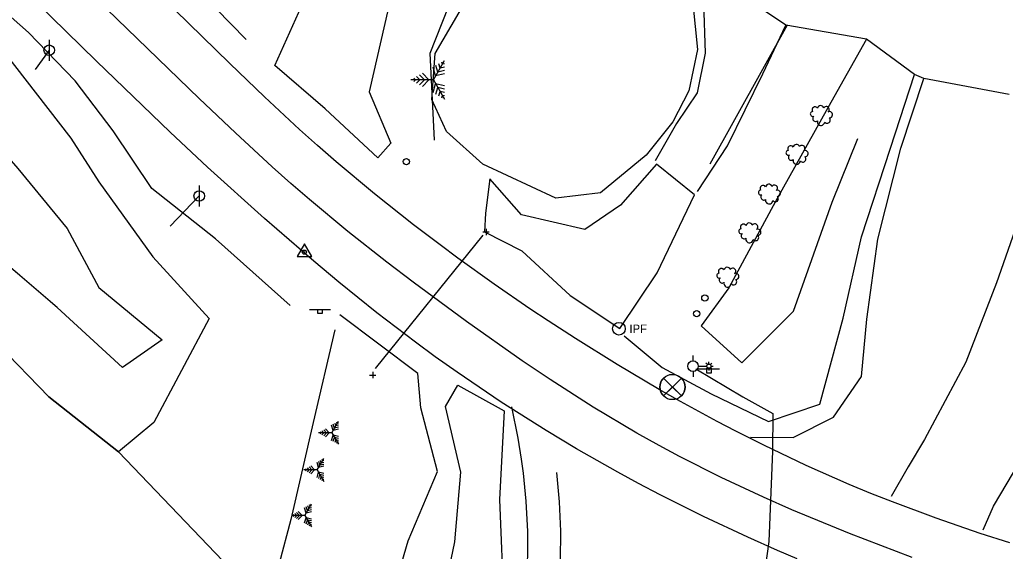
# Model space of a CAD drawing. Extents: x 1158469 to 1165378, y 609843 to 611748.
# Drawn here: x 1158676 to 1158909.5, y 611390 to 611516 of the extents above; entities that cross this region are included whole.
import ezdxf

# ---------------------------------------------------------------- set-up
doc = ezdxf.new("R2010")
doc.units = 0
for name, color, linetype in [('Exterior Boundary', 7, 'Continuous'), ('S_Control_Temp_Traverse', 7, 'Continuous'), ('S_Drainage_Culvert_Top', 7, 'Continuous'), ('S_Drainage_Invert', 7, 'Continuous'), ('S_Drainage_Waterway', 7, 'Continuous'), ('S_Fencing_Page', 7, 'Continuous'), ('S_Ground_Elevation', 7, 'Continuous'), ('S_Property_IronPipeFound', 7, 'Continuous'), ('S_Roadway_Centerline', 7, 'Continuous'), ('S_Roadway_Drive_Gravel', 7, 'Continuous'), ('S_Roadway_Edge_Pavement', 7, 'Continuous'), ('S_Roadway_Edge_TW', 7, 'Continuous'), ('S_Traffic_Post_Conc', 7, 'Continuous'), ('S_Traffic_Sign_SinglePost', 7, 'Continuous'), ('S_Trees_Bush', 7, 'Continuous'), ('S_Trees_Conifer_NonPay', 7, 'Continuous'), ('S_Trees_Conifer_Pay', 7, 'Continuous'), ('S_Trees_HedgeLine', 7, 'Continuous'), ('S_Utilities_GuyWire3', 7, 'Continuous'), ('S_Utilities_Pole_Power', 7, 'Continuous'), ('S_Utilities_Pole_StreetLight', 7, 'Continuous'), ('S_Utilities_UG_BoringLocation', 7, 'Continuous'), ('S_Utilities_UG_Electrical_Line', 7, 'Continuous')]:
    doc.layers.add(name, color=color, linetype=linetype)

msp = doc.modelspace()

# ---------------------------------------------------------------- linework, layer by layer
at = {"layer": 'Exterior Boundary'}
for points in [[(1158910.45, 611498.3), (1158890.25, 611502.09), (1158888.06, 611503.01), (1158876.65, 611511.4), (1158857.5, 611514.75), (1158825.21, 611536.33)], [(1158670.67, 611439.15), (1158682.9, 611426.67), (1158699.39, 611413.61), (1158734.7, 611376.73), (1158730.76, 611361.06), (1158748.32, 611349.64), (1158760.71, 611343.05), (1158765.36, 611317.58), (1158768.71, 611314.29), (1158775.07, 611309.36), (1158788.22, 611303.65), (1158800.68, 611297.03), (1158808.24, 611293.89), (1158811.71, 611292.65), (1158828.39, 611280.44), (1158844.21, 611270.14), (1158861.97, 611263.38), (1158876.73, 611255.65), (1158889.33, 611276.16), (1158914.58, 611278.16)]]:
    msp.add_lwpolyline(points, dxfattribs=at)
at = {"layer": 'S_Control_Temp_Traverse'}
for p, q in [((1158743.3, 611460.92), (1158743.55, 611460.92)), ((1158743.42, 611461.05), (1158743.42, 611460.8))]:
    msp.add_line(p, q, dxfattribs=at)
msp.add_lwpolyline([(1158741.69, 611459.92), (1158745.16, 611459.92), (1158743.42, 611462.92)], close=True, dxfattribs=at)
msp.add_circle((1158743.42, 611460.92), 0.5, dxfattribs=at)
at = {"layer": 'S_Drainage_Culvert_Top'}
msp.add_lwpolyline([(1158785.74, 611464.98), (1158760.24, 611433.33)], dxfattribs=at)
at = {"layer": 'S_Drainage_Invert'}
for p, q in [((1158785.73, 611465.71), (1158787.23, 611465.71)), ((1158786.48, 611466.46), (1158786.48, 611464.96)), ((1158758.88, 611431.79), (1158760.38, 611431.79)), ((1158759.63, 611432.54), (1158759.63, 611431.04))]:
    msp.add_line(p, q, dxfattribs=at)
at = {"layer": 'S_Drainage_Waterway'}
msp.add_lwpolyline([(1158785.74, 611481.8), (1158777.15, 611489.55), (1158773.6, 611497.1), (1158774.43, 611508), (1158780.14, 611517.71), (1158786.58, 611529.17), (1158799.68, 611540.94), (1158809.55, 611542.02), (1158823.95, 611534.62), (1158835.49, 611519.84), (1158836.62, 611508.98), (1158834.58, 611499.17), (1158830.73, 611491.78), (1158824.45, 611483.92), (1158813.6, 611474.99), (1158803.06, 611473.68)], close=True, dxfattribs=at)
at = {"layer": 'S_Fencing_Page'}
msp.add_lwpolyline([(1158750.67, 611442.48), (1158745.54, 611420.52), (1158740.24, 611397.56), (1158734.7, 611376.73), (1158730.76, 611361.06)], dxfattribs=at)
at = {"layer": 'S_Ground_Elevation'}
for points in [[(1158740.09, 611448.28), (1158722.35, 611464.08), (1158707.31, 611475.97), (1158698.09, 611489.64), (1158689.14, 611501.5), (1158678.07, 611512.98), (1158662.14, 611527.03), (1158643.93, 611543.97), (1158624.15, 611563.13), (1158596.77, 611589.62)], [(1158808.66, 611546.24), (1158790.91, 611556.33), (1158774.35, 611541), (1158763.38, 611518.91), (1158758.8, 611498.89), (1158763.92, 611486.74), (1158760.8, 611483.29), (1158748.32, 611494.91), (1158736.46, 611505.19), (1158743.56, 611521.02), (1158754.04, 611539.22), (1158761.64, 611558.27), (1158767.55, 611571.39), (1158747.46, 611585.83), (1158737.58, 611570.89), (1158726.51, 611554.87), (1158719.26, 611542.74), (1158716.56, 611529.56), (1158722.45, 611518.66), (1158729.61, 611511.28)], [(1158590.85, 611583.59), (1158615.18, 611558.04), (1158629.09, 611543.1), (1158650.93, 611520), (1158669.17, 611512.21), (1158688.09, 611487.97), (1158694.7, 611477.56), (1158707.55, 611459.8), (1158720.85, 611445.22), (1158707.76, 611420.56), (1158699.39, 611413.61), (1158682.9, 611426.67), (1158670.67, 611439.15), (1158654.72, 611451.38), (1158635.01, 611471.5), (1158613.25, 611484.43), (1158585.12, 611500.58), (1158568.33, 611515.58)], [(1158580.71, 611570.3), (1158596.17, 611552.09), (1158620.52, 611526.83), (1158638.48, 611508.6), (1158660.2, 611498.31), (1158675.5, 611480.75), (1158687.22, 611466.53), (1158694.73, 611452.55), (1158709.71, 611440.16), (1158700.35, 611433.55), (1158684.85, 611447.82), (1158665.43, 611464.41), (1158653.02, 611480.25), (1158622.81, 611498.8), (1158603.19, 611517), (1158575.66, 611532.02), (1158562.58, 611545.77)], [(1158774.24, 611487.44), (1158773.21, 611508.05), (1158777.62, 611519.03), (1158785.53, 611530.88), (1158792.69, 611538.6), (1158803.21, 611544.63), (1158811.27, 611543.77), (1158825.21, 611536.33), (1158838.01, 611520.07), (1158838.43, 611508.04), (1158836.52, 611498.69), (1158831.59, 611491.44), (1158826.6, 611482.59)], [(1158836.58, 611475.29), (1158843.71, 611486.11), (1158852.11, 611503.19), (1158857.5, 611514.75)], [(1158819.2, 611441.05), (1158828.22, 611433.55), (1158839.8, 611427.34), (1158853.43, 611420.78), (1158865.56, 611424.89), (1158871.1, 611445.26), (1158875.5, 611464.56), (1158882.32, 611485.55), (1158888.06, 611503.01), (1158876.65, 611511.4), (1158867.51, 611495.16), (1158855.12, 611472.93), (1158844, 611452.47), (1158837.45, 611443.47), (1158847.09, 611434.67), (1158859.35, 611446.93), (1158868.53, 611472.76), (1158874.57, 611487.84)], [(1158904.32, 611395.15), (1158906.79, 611400.72), (1158916.02, 611416.31), (1158924.09, 611434.05), (1158932.36, 611453.59), (1158941.22, 611470.3), (1158947.06, 611480.27), (1158932.94, 611486.27), (1158930.52, 611481.92), (1158922.93, 611484.99), (1158913.99, 611472.35), (1158907.43, 611453.65), (1158900.18, 611434.86), (1158890.38, 611416.5), (1158886.53, 611410.08), (1158882.51, 611403.01)], [(1158748.32, 611349.64), (1158761.67, 611370.85), (1158768.02, 611392.49), (1158774.99, 611408.97), (1158771.02, 611424.01), (1158770.29, 611432.13), (1158751.86, 611446.05)], [(1158750.67, 611442.48), (1158745.54, 611420.52), (1158740.24, 611397.56), (1158734.7, 611376.73), (1158730.76, 611361.06)], [(1158760.71, 611343.05), (1158773.56, 611365.65), (1158779.05, 611392.3), (1158780.47, 611408.74), (1158776.85, 611424.34), (1158779.76, 611429.39), (1158790.77, 611423.33), (1158789.65, 611402.27), (1158790.72, 611377.04), (1158784.12, 611354), (1158765.36, 611317.58)]]:
    msp.add_lwpolyline(points, dxfattribs=at)
msp.add_lwpolyline([(1158787.4, 611478.32), (1158786.33, 611470.19), (1158786.11, 611465.72), (1158794.97, 611461.22), (1158806.44, 611450.67), (1158818.21, 611442.8), (1158827.03, 611456.05), (1158835.92, 611474.48), (1158826.85, 611481.78), (1158818.38, 611472.07), (1158809.87, 611466.29), (1158794.88, 611469.73)], close=True, dxfattribs=at)
at = {"layer": 'S_Property_IronPipeFound'}
msp.add_circle((1158817.97, 611442.76), 1.5, dxfattribs=at)
at = {"layer": 'S_Roadway_Centerline'}
msp.add_lwpolyline([(1158887.44, 611388.58), (1158872.59, 611394.24), (1158858.97, 611399.85), (1158852.23, 611402.82), (1158842.21, 611407.49), (1158832.35, 611412.46), (1158827.48, 611415.07), (1158822.23, 611418.02), (1158811.88, 611424.2), (1158801.72, 611430.71), (1158795.04, 611435.2), (1158781.87, 611444.46), (1158769.21, 611453.77), (1158762.97, 611458.54), (1158753.73, 611465.84), (1158744.68, 611473.36), (1158740.23, 611477.2), (1158735.8, 611481.14), (1158727.08, 611489.17), (1158718.49, 611497.35), (1158701.46, 611513.88), (1158679.55, 611535.06)], dxfattribs=at)
at = {"layer": 'S_Roadway_Drive_Gravel'}
msp.add_lwpolyline([(1158849.13, 611417.04), (1158859.3, 611417), (1158868.8, 611421.81), (1158875.5, 611431.43), (1158876.76, 611445.05), (1158879.32, 611463.97), (1158884.77, 611485.57), (1158890.25, 611502.09)], dxfattribs=at)
at = {"layer": 'S_Roadway_Edge_Pavement'}
for points in [[(1158910.66, 611392.01), (1158903.63, 611394.28), (1158893.17, 611397.88), (1158882.8, 611401.72), (1158877.66, 611403.76), (1158872.53, 611405.88), (1158862.36, 611410.37), (1158852.3, 611415.16), (1158845.67, 611418.51), (1158841.28, 611420.81), (1158832.59, 611425.54), (1158827.53, 611428.4), (1158817.53, 611434.31), (1158807.67, 611440.44), (1158801.17, 611444.65), (1158796.88, 611447.52), (1158788.37, 611453.36), (1158779.82, 611459.49), (1158775.6, 611462.62), (1158769.32, 611467.39), (1158760.05, 611474.74), (1158750.98, 611482.33), (1158746.53, 611486.22), (1158742.29, 611490.01), (1158733.95, 611497.75), (1158725.73, 611505.63), (1158709.47, 611521.56)], [(1158860.25, 611388.2), (1158855.54, 611390.23), (1158848.51, 611393.36), (1158838.06, 611398.26), (1158827.73, 611403.43), (1158822.62, 611406.11), (1158817.69, 611408.78), (1158807.93, 611414.32), (1158800.71, 611418.64), (1158790.05, 611425.4), (1158779.6, 611432.47), (1158774.46, 611436.12), (1158769.8, 611439.55), (1158760.6, 611446.57), (1158751.58, 611453.82), (1158745.66, 611458.76), (1158733.99, 611468.86), (1158720.5, 611481.08), (1158711.64, 611489.37), (1158694.13, 611506.17), (1158679.83, 611520.15)], [(1158792.52, 611424.23), (1158794.05, 611416.81), (1158794.84, 611411.85), (1158795.28, 611408.54), (1158795.92, 611401.88), (1158796.28, 611394.7), (1158796.32, 611391.1), (1158796.21, 611385.69), (1158795.87, 611380.29), (1158795.62, 611377.6), (1158794.95, 611372.37), (1158794.51, 611369.78), (1158793.7, 611365.91), (1158792.67, 611362.1), (1158792.08, 611360.21), (1158790.69, 611356.49), (1158789.9, 611354.66), (1158788.57, 611351.95), (1158768.71, 611314.29)]]:
    msp.add_lwpolyline(points, dxfattribs=at)
at = {"layer": 'S_Roadway_Edge_TW'}
msp.add_lwpolyline([(1158803.15, 611408.66), (1158803.84, 611401.73), (1158804.14, 611394.77), (1158804.03, 611387.81), (1158803.52, 611380.86), (1158802.62, 611373.95), (1158801.32, 611367.11), (1158799.63, 611360.35), (1158797.56, 611353.7), (1158795.53, 611348.23), (1158775.07, 611309.36)], dxfattribs=at)
at = {"layer": 'S_Traffic_Post_Conc'}
for centre in [(1158767.61, 611482.38), (1158838.34, 611450.05), (1158836.42, 611446.34)]:
    msp.add_circle(centre, 0.75, dxfattribs=at)
at = {"layer": 'S_Traffic_Sign_SinglePost'}
for p, q in [((1158744.65, 611447.36), (1158749.65, 611447.36)), ((1158836.83, 611433.27), (1158841.83, 611433.27))]:
    msp.add_line(p, q, dxfattribs=at)
for points in [[(1158746.65, 611447.36), (1158747.65, 611447.36), (1158747.65, 611446.36), (1158746.65, 611446.36)], [(1158838.83, 611433.27), (1158839.83, 611433.27), (1158839.83, 611432.27), (1158838.83, 611432.27)]]:
    msp.add_lwpolyline(points, close=True, dxfattribs=at)
at = {"layer": 'S_Trees_Bush'}
for centre, radius, start, end in [((1158864.45, 611494.64), 0.717, 33.6405, 213.5909), ((1158865.81, 611494.88), 0.776, 19.7277, 168.0032), ((1158867.13, 611494.73), 0.715, 304.7168, 145.2832), ((1158863.91, 611493.67), 0.576, 95.1875, 295.4615), ((1158864.6, 611492.6), 0.706, 129.1555, 309.4105), ((1158867.33, 611492.21), 0.742, 216.9809, 47.4965), ((1158867.85, 611493.49), 0.733, 268.122, 116.0172), ((1158865.88, 611491.82), 0.862, 163.7427, 356.276), ((1158858.69, 611485.43), 0.717, 33.6405, 213.5909), ((1158860.05, 611485.67), 0.776, 19.7277, 168.0032), ((1158861.36, 611485.52), 0.715, 304.7168, 145.2832), ((1158858.14, 611484.46), 0.576, 95.1875, 295.4615), ((1158858.84, 611483.4), 0.706, 129.1555, 309.4105), ((1158861.57, 611483), 0.742, 216.9809, 47.4965), ((1158862.09, 611484.28), 0.733, 268.122, 116.0172), ((1158860.11, 611482.61), 0.862, 163.7427, 356.276), ((1158852.15, 611476.01), 0.717, 33.6405, 213.5909), ((1158853.51, 611476.25), 0.776, 19.7277, 168.0032), ((1158854.82, 611476.1), 0.715, 304.7168, 145.2832), ((1158851.61, 611475.04), 0.576, 95.1875, 295.4615), ((1158852.3, 611473.97), 0.706, 129.1555, 309.4105), ((1158855.03, 611473.58), 0.742, 216.9809, 47.4965), ((1158855.55, 611474.86), 0.733, 268.122, 116.0172), ((1158853.58, 611473.19), 0.862, 163.7427, 356.276), ((1158847.5, 611466.82), 0.717, 33.6405, 213.5909), ((1158848.85, 611467.06), 0.776, 19.7277, 168.0032), ((1158850.17, 611466.91), 0.715, 304.7168, 145.2832), ((1158846.95, 611465.85), 0.576, 95.1875, 295.4615), ((1158847.65, 611464.78), 0.706, 129.1555, 309.4105), ((1158848.92, 611463.99), 0.862, 163.7427, 356.276), ((1158850.38, 611464.38), 0.742, 216.9809, 47.4965), ((1158850.9, 611465.66), 0.733, 268.122, 116.0172), ((1158843.64, 611456.57), 0.776, 19.7277, 168.0032), ((1158841.74, 611455.36), 0.576, 95.1875, 295.4615), ((1158842.28, 611456.33), 0.717, 33.6405, 213.5909), ((1158842.43, 611454.3), 0.706, 129.1555, 309.4105), ((1158844.96, 611456.42), 0.715, 304.7168, 145.2832), ((1158845.69, 611455.18), 0.733, 268.122, 116.0172), ((1158843.71, 611453.51), 0.862, 163.7427, 356.276), ((1158845.16, 611453.9), 0.742, 216.9809, 47.4965)]:
    msp.add_arc(centre, radius, start, end, dxfattribs=at)
at = {"layer": 'S_Trees_Conifer_NonPay'}
for p, q in [((1158750.25, 611418.65), (1158749.89, 611419.9)), ((1158749.93, 611418.11), (1158751.51, 611420.83)), ((1158750.56, 611419.2), (1158750.29, 611420.13)), ((1158750.88, 611419.74), (1158750.7, 611420.36)), ((1158751.51, 611419.9), (1158750.88, 611419.74)), ((1158751.19, 611420.28), (1158751.1, 611420.6)), ((1158751.51, 611420.36), (1158751.19, 611420.28)), ((1158749.93, 611418.11), (1158746.79, 611418.11)), ((1158747.42, 611418.11), (1158747.19, 611418.34)), ((1158747.19, 611417.88), (1158747.42, 611418.11)), ((1158748.05, 611418.11), (1158747.6, 611418.57)), ((1158747.6, 611417.64), (1158748.05, 611418.11)), ((1158748.68, 611418.11), (1158748, 611418.81)), ((1158748, 611417.41), (1158748.68, 611418.11)), ((1158749.3, 611418.11), (1158748.41, 611419.04)), ((1158748.41, 611417.18), (1158749.3, 611418.11)), ((1158749.89, 611416.32), (1158750.25, 611417.56)), ((1158749.93, 611418.11), (1158751.51, 611415.39)), ((1158751.51, 611418.96), (1158750.25, 611418.65)), ((1158751.51, 611417.25), (1158750.25, 611417.56)), ((1158751.51, 611419.43), (1158750.56, 611419.2)), ((1158750.29, 611416.09), (1158750.56, 611417.02)), ((1158751.51, 611416.79), (1158750.56, 611417.02)), ((1158750.7, 611415.85), (1158750.88, 611416.47)), ((1158751.51, 611416.32), (1158750.88, 611416.47)), ((1158751.1, 611415.62), (1158751.19, 611415.93)), ((1158751.51, 611415.85), (1158751.19, 611415.93)), ((1158746.78, 611409.85), (1158746.42, 611411.1)), ((1158746.46, 611409.31), (1158748.03, 611412.03)), ((1158747.09, 611410.4), (1158746.82, 611411.33)), ((1158748.03, 611410.63), (1158747.09, 611410.4)), ((1158747.4, 611410.94), (1158747.23, 611411.56)), ((1158748.03, 611411.1), (1158747.4, 611410.94)), ((1158747.72, 611411.48), (1158747.63, 611411.8)), ((1158748.03, 611411.56), (1158747.72, 611411.48)), ((1158746.46, 611409.31), (1158743.32, 611409.31)), ((1158743.95, 611409.31), (1158743.72, 611409.54)), ((1158743.72, 611409.08), (1158743.95, 611409.31)), ((1158744.58, 611409.31), (1158744.13, 611409.77)), ((1158744.13, 611408.84), (1158744.58, 611409.31)), ((1158745.2, 611409.31), (1158744.53, 611410.01)), ((1158744.53, 611408.61), (1158745.2, 611409.31)), ((1158745.83, 611409.31), (1158744.93, 611410.24)), ((1158744.93, 611408.38), (1158745.83, 611409.31)), ((1158746.42, 611407.52), (1158746.78, 611408.76)), ((1158746.46, 611409.31), (1158748.03, 611406.59)), ((1158748.03, 611410.16), (1158746.78, 611409.85)), ((1158748.03, 611408.45), (1158746.78, 611408.76)), ((1158746.82, 611407.29), (1158747.09, 611408.22)), ((1158748.03, 611407.99), (1158747.09, 611408.22)), ((1158747.23, 611407.05), (1158747.4, 611407.67)), ((1158748.03, 611407.52), (1158747.4, 611407.67)), ((1158747.63, 611406.82), (1158747.72, 611407.13)), ((1158748.03, 611407.05), (1158747.72, 611407.13)), ((1158743.51, 611398.53), (1158745.08, 611401.25)), ((1158741.63, 611398.53), (1158741.18, 611398.99)), ((1158742.26, 611398.53), (1158741.58, 611399.23)), ((1158742.88, 611398.53), (1158741.99, 611399.46)), ((1158743.83, 611399.07), (1158743.47, 611400.32)), ((1158745.08, 611399.38), (1158743.83, 611399.07)), ((1158744.14, 611399.61), (1158743.87, 611400.55)), ((1158745.08, 611399.85), (1158744.14, 611399.61)), ((1158744.46, 611400.16), (1158744.28, 611400.78)), ((1158745.08, 611400.32), (1158744.46, 611400.16)), ((1158744.77, 611400.7), (1158744.68, 611401.02)), ((1158745.08, 611400.78), (1158744.77, 611400.7)), ((1158743.51, 611398.53), (1158740.37, 611398.53)), ((1158741, 611398.53), (1158740.77, 611398.76)), ((1158740.77, 611398.29), (1158741, 611398.53)), ((1158741.18, 611398.06), (1158741.63, 611398.53)), ((1158741.58, 611397.83), (1158742.26, 611398.53)), ((1158741.99, 611397.59), (1158742.88, 611398.53)), ((1158743.47, 611396.74), (1158743.83, 611397.98)), ((1158743.51, 611398.53), (1158745.08, 611395.8)), ((1158745.08, 611397.67), (1158743.83, 611397.98)), ((1158743.87, 611396.51), (1158744.14, 611397.44)), ((1158745.08, 611397.21), (1158744.14, 611397.44)), ((1158744.28, 611396.27), (1158744.46, 611396.89)), ((1158745.08, 611396.74), (1158744.46, 611396.89)), ((1158744.68, 611396.04), (1158744.77, 611396.35)), ((1158745.08, 611396.27), (1158744.77, 611396.35))]:
    msp.add_line(p, q, dxfattribs=at)
at = {"layer": 'S_Trees_Conifer_Pay'}
for p, q in [((1158774, 611501.76), (1158776.67, 611506.38)), ((1158774.53, 611502.68), (1158773.92, 611504.79)), ((1158775.07, 611503.61), (1158774.61, 611505.19)), ((1158776.67, 611504), (1158775.07, 611503.61)), ((1158775.6, 611504.53), (1158775.3, 611505.59)), ((1158776.67, 611504.79), (1158775.6, 611504.53)), ((1158776.13, 611505.45), (1158775.98, 611505.98)), ((1158776.67, 611505.59), (1158776.13, 611505.45)), ((1158774, 611501.76), (1158768.66, 611501.76)), ((1158769.73, 611501.76), (1158769.35, 611502.15)), ((1158769.35, 611501.36), (1158769.73, 611501.76)), ((1158770.8, 611501.76), (1158770.04, 611502.55)), ((1158770.04, 611500.97), (1158770.8, 611501.76)), ((1158771.87, 611501.76), (1158770.72, 611502.95)), ((1158770.72, 611500.57), (1158771.87, 611501.76)), ((1158772.93, 611501.76), (1158771.41, 611503.34)), ((1158771.41, 611500.17), (1158772.93, 611501.76)), ((1158774, 611501.76), (1158776.67, 611497.14)), ((1158776.67, 611503.21), (1158774.53, 611502.68)), ((1158773.92, 611498.72), (1158774.53, 611500.83)), ((1158776.67, 611500.31), (1158774.53, 611500.83)), ((1158774.61, 611498.33), (1158775.07, 611499.91)), ((1158776.67, 611499.51), (1158775.07, 611499.91)), ((1158775.3, 611497.93), (1158775.6, 611498.99)), ((1158776.67, 611498.72), (1158775.6, 611498.99)), ((1158775.98, 611497.53), (1158776.13, 611498.06)), ((1158776.67, 611497.93), (1158776.13, 611498.06))]:
    msp.add_line(p, q, dxfattribs=at)
at = {"layer": 'S_Trees_HedgeLine'}
msp.add_lwpolyline([(1158857.84, 611514.72), (1158839.53, 611481.8)], dxfattribs=at)
at = {"layer": 'S_Utilities_GuyWire3'}
for points in [[(1158682.96, 611508.77), (1158679.61, 611504.19)], [(1158718.51, 611474.23), (1158711.63, 611467.08)]]:
    msp.add_lwpolyline(points, dxfattribs=at)
at = {"layer": 'S_Utilities_Pole_Power'}
for p, q in [((1158682.96, 611511.27), (1158682.96, 611506.27)), ((1158718.51, 611476.73), (1158718.51, 611471.73))]:
    msp.add_line(p, q, dxfattribs=at)
for centre in [(1158682.96, 611508.77), (1158718.51, 611474.23)]:
    msp.add_circle(centre, 1.25, dxfattribs=at)
at = {"layer": 'S_Utilities_Pole_StreetLight'}
for p, q in [((1158835.54, 611435.15), (1158835.54, 611436.4)), ((1158836.79, 611433.9), (1158838.79, 611433.9)), ((1158838.94, 611434.26), (1158838.59, 611434.61)), ((1158839.29, 611434.4), (1158839.29, 611434.9)), ((1158839.65, 611434.26), (1158840, 611434.61)), ((1158839.79, 611433.9), (1158840.29, 611433.9)), ((1158835.54, 611432.65), (1158835.54, 611431.4)), ((1158838.94, 611433.55), (1158838.59, 611433.2)), ((1158839.29, 611433.4), (1158839.29, 611432.9)), ((1158839.65, 611433.55), (1158840, 611433.2))]:
    msp.add_line(p, q, dxfattribs=at)
for centre, radius in [((1158835.54, 611433.9), 1.25), ((1158839.29, 611433.9), 0.5)]:
    msp.add_circle(centre, radius, dxfattribs=at)
at = {"layer": 'S_Utilities_UG_BoringLocation'}
for p, q in [((1158828.54, 611431.08), (1158832.78, 611426.84)), ((1158828.54, 611426.84), (1158832.78, 611431.08))]:
    msp.add_line(p, q, dxfattribs=at)
for points in [[(1158828.54, 611426.84), (1158830.66, 611428.96), (1158828.54, 611431.08)], [(1158832.78, 611431.08), (1158830.66, 611428.96), (1158832.78, 611426.84)]]:
    msp.add_lwpolyline(points, dxfattribs=at)
msp.add_circle((1158830.66, 611428.96), 3, dxfattribs=at)
for start, end in [(135, 225), (315, 45)]:
    msp.add_arc((1158830.66, 611428.96), 3, start, end, dxfattribs=at)
at = {"layer": 'S_Utilities_UG_Electrical_Line'}
msp.add_lwpolyline([(1158836.24, 611433.29), (1158847.37, 611426.66), (1158854.42, 611422.66), (1158854.37, 611413.77), (1158853.51, 611392.37), (1158850.63, 611371.87), (1158849.84, 611364.84)], dxfattribs=at)

# ---------------------------------------------------------------- texts
at = {"layer": 'S_Property_IronPipeFound'}
msp.add_text('IPF', height=2, dxfattribs=at).set_placement((1158820.47, 611441.76))

doc.saveas('drawing.dxf')
